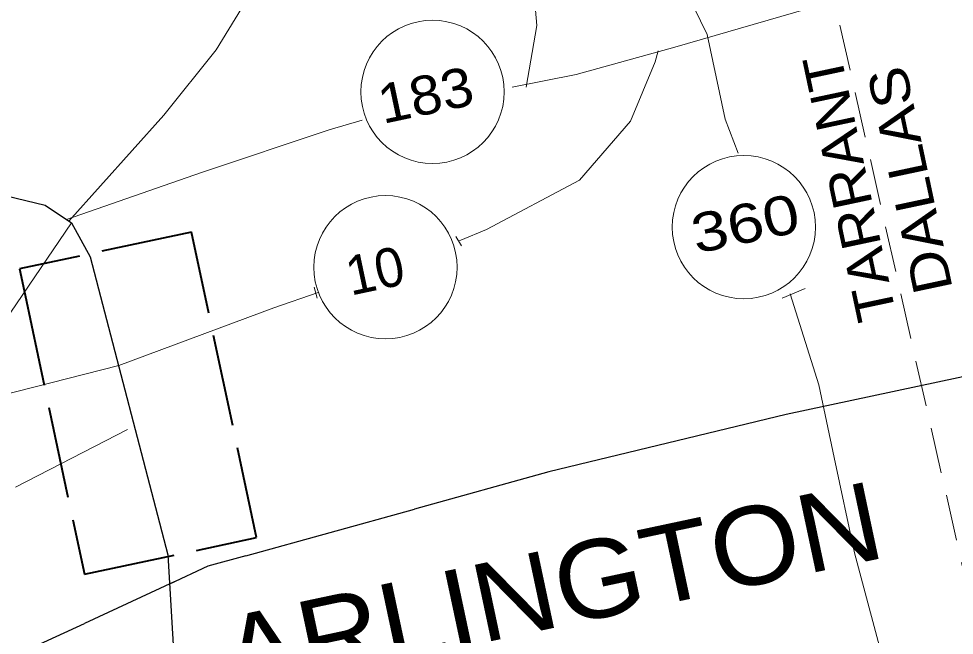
# Model space of a CAD drawing. Extents: x 2357218 to 2371708, y 6973728 to 6980157.
# Drawn here: x 2357522.9 to 2357645.2, y 6974667.5 to 6974748.1 of the extents above; entities that cross this region are included whole.
import ezdxf

# ---------------------------------------------------------------- set-up
doc = ezdxf.new("R2010")
doc.units = 0
doc.header["$LTSCALE"] = 2
doc.linetypes.add('LONG_DASHED', pattern=[7.5, 6, -1.5])
doc.linetypes.add('MEDIUM_DASHED', pattern=[4.5, 3, -1.5])
doc.layers.add('62', color=7, linetype='Continuous', lineweight=13)
doc.layers.add('63', color=7, linetype='Continuous', lineweight=13)

msp = doc.modelspace()

# ---------------------------------------------------------------- linework, layer by layer
at = {"layer": '62', "linetype": 'MEDIUM_DASHED'}
msp.add_line((2357608.391, 6974843.78), (2357670.463, 6974569.716), dxfattribs=at)
at = {"layer": '62'}
for p, q in [((2357548.716, 6974744.002), (2357555.342, 6974754.934)), ((2357612.906, 6974746.026), (2357615.266, 6974734.934)), ((2357606.095, 6974742.461), (2357606.484, 6974743.878)), ((2357595.779, 6974740.777), (2357587.405, 6974739.157)), ((2357563.473, 6974733.564), (2357567.781, 6974734.825)), ((2357615.266, 6974734.934), (2357616.963, 6974730.511)), ((2357529.782, 6974721.388), (2357494.082, 6974668.875)), ((2357584.049, 6974720.525), (2357580.707, 6974719.146)), ((2357580.057, 6974719.607), (2357580.778, 6974718.38)), ((2357580.386, 6974719.031), (2357580.707, 6974719.146)), ((2357561.523, 6974712.977), (2357561.915, 6974711.566)), ((2357622.696, 6974711.552), (2357625.691, 6974712.833)), ((2357556.226, 6974710.287), (2357562.056, 6974712.306)), ((2357627.492, 6974700.242), (2357623.746, 6974712.121)), ((2357528.402, 6974689.897), (2357537.133, 6974694.379)), ((2357522.449, 6974686.841), (2357528.402, 6974689.897))]:
    msp.add_line(p, q, dxfattribs=at)
at = {"layer": '62', "lineweight": 25}
for p, q in [((2357529.782, 6974721.388), (2357532.218, 6974716.961)), ((2357532.218, 6974716.962), (2357542.389, 6974677.99)), ((2357552.581, 6974677.856), (2357574.636, 6974683.971)), ((2357543.23, 6974674.464), (2357531.481, 6974669.021)), ((2357525.137, 6974666.085), (2357531.481, 6974669.021))]:
    msp.add_line(p, q, dxfattribs=at)
at = {"layer": '62'}
for points in [[(2357612.906, 6974746.026), (2357600.131, 6974772.25), (2357585.724, 6974789.274)], [(2357595.779, 6974740.777), (2357608.657, 6974744.365), (2357631.126, 6974750.887), (2357652.256, 6974754.413), (2357666.337, 6974756.671), (2357684.011, 6974760.219), (2357693.6, 6974764.79), (2357703.731, 6974774.259), (2357715.298, 6974783.597), (2357718.976, 6974785.553)], [(2357589.228, 6974739.131), (2357590.624, 6974747.179), (2357590.131, 6974752.736)], [(2357548.716, 6974744.002), (2357541.879, 6974735.46), (2357529.457, 6974721.619)], [(2357584.049, 6974720.525), (2357596.207, 6974726.972), (2357602.867, 6974734.714), (2357606.095, 6974742.461)], [(2357529.137, 6974721.827), (2357546.802, 6974727.997), (2357563.473, 6974733.564)], [(2357556.226, 6974710.287), (2357535.978, 6974702.736), (2357489.081, 6974690.789), (2357482.118, 6974688.043)], [(2357627.492, 6974700.242), (2357629.511, 6974690.734), (2357632.166, 6974678.254), (2357636.479, 6974662.08)]]:
    msp.add_lwpolyline(points, dxfattribs=at)
at = {"layer": '62', "lineweight": 25}
for points in [[(2357731.323, 6974727.465), (2357718.735, 6974723.478), (2357699.754, 6974716.569), (2357676.809, 6974708.817), (2357651.65, 6974702.388), (2357623.234, 6974696.348), (2357592.187, 6974688.85), (2357574.636, 6974683.971)], [(2357426.636, 6974677.632), (2357435.051, 6974686.092), (2357447.82, 6974693.662), (2357456.605, 6974700.382), (2357465.446, 6974706.953), (2357476.319, 6974714.14), (2357482.491, 6974718.329), (2357492.265, 6974720.406), (2357507.868, 6974723.722), (2357519.974, 6974725.216), (2357526.369, 6974723.698), (2357529.782, 6974721.388)], [(2357542.389, 6974677.989), (2357543.196, 6974664.013), (2357544.313, 6974651.62)], [(2357552.581, 6974677.856), (2357547.604, 6974676.5), (2357542.602, 6974674.17)]]:
    msp.add_lwpolyline(points, dxfattribs=at)
at = {"layer": '62', "linetype": 'LONG_DASHED', "lineweight": 40}
msp.add_lwpolyline([(2357523.717, 6974711.934), (2357531.47, 6974675.463), (2357553.987, 6974680.247), (2357545.5, 6974720.173), (2357522.983, 6974715.389)], close=True, dxfattribs=at)
at = {"layer": '62'}
for centre in [(2357576.995, 6974738.519), (2357617.695, 6974720.846), (2357570.841, 6974715.596)]:
    msp.add_circle(centre, 9.364, dxfattribs=at)
at = {"layer": '63', "linetype": 'MEDIUM_DASHED'}
msp.add_line((2357608.391, 6974843.78), (2357670.463, 6974569.716), dxfattribs=at)
at = {"layer": '63'}
for p, q in [((2357548.716, 6974744.002), (2357555.342, 6974754.934)), ((2357612.906, 6974746.026), (2357615.266, 6974734.934)), ((2357606.095, 6974742.461), (2357606.484, 6974743.878)), ((2357595.779, 6974740.777), (2357587.405, 6974739.157)), ((2357563.473, 6974733.564), (2357567.781, 6974734.825)), ((2357615.266, 6974734.934), (2357616.963, 6974730.511)), ((2357529.782, 6974721.388), (2357494.082, 6974668.875)), ((2357584.049, 6974720.525), (2357580.707, 6974719.146)), ((2357580.057, 6974719.607), (2357580.778, 6974718.38)), ((2357580.386, 6974719.031), (2357580.707, 6974719.146)), ((2357561.523, 6974712.977), (2357561.915, 6974711.566)), ((2357622.696, 6974711.552), (2357625.691, 6974712.833)), ((2357556.226, 6974710.287), (2357562.056, 6974712.306)), ((2357627.492, 6974700.242), (2357623.746, 6974712.121)), ((2357528.402, 6974689.897), (2357537.133, 6974694.379)), ((2357522.449, 6974686.841), (2357528.402, 6974689.897))]:
    msp.add_line(p, q, dxfattribs=at)
at = {"layer": '63', "lineweight": 25}
for p, q in [((2357529.782, 6974721.388), (2357532.218, 6974716.961)), ((2357532.218, 6974716.962), (2357542.389, 6974677.99)), ((2357552.581, 6974677.856), (2357574.636, 6974683.971)), ((2357543.23, 6974674.464), (2357531.481, 6974669.021)), ((2357525.137, 6974666.085), (2357531.481, 6974669.021))]:
    msp.add_line(p, q, dxfattribs=at)
at = {"layer": '63'}
for points in [[(2357612.906, 6974746.026), (2357600.131, 6974772.25), (2357585.724, 6974789.274)], [(2357595.779, 6974740.777), (2357608.657, 6974744.365), (2357631.126, 6974750.887), (2357652.256, 6974754.413), (2357666.337, 6974756.671), (2357684.011, 6974760.219), (2357693.6, 6974764.79), (2357703.731, 6974774.259), (2357715.298, 6974783.597), (2357718.976, 6974785.553)], [(2357589.228, 6974739.131), (2357590.624, 6974747.179), (2357590.131, 6974752.736)], [(2357548.716, 6974744.002), (2357541.879, 6974735.46), (2357529.457, 6974721.619)], [(2357584.049, 6974720.525), (2357596.207, 6974726.972), (2357602.867, 6974734.714), (2357606.095, 6974742.461)], [(2357529.137, 6974721.827), (2357546.802, 6974727.997), (2357563.473, 6974733.564)], [(2357556.226, 6974710.287), (2357535.978, 6974702.736), (2357489.081, 6974690.789), (2357482.118, 6974688.043)], [(2357627.492, 6974700.242), (2357629.511, 6974690.734), (2357632.166, 6974678.254), (2357636.479, 6974662.08)]]:
    msp.add_lwpolyline(points, dxfattribs=at)
at = {"layer": '63', "lineweight": 25}
for points in [[(2357731.323, 6974727.465), (2357718.735, 6974723.478), (2357699.754, 6974716.569), (2357676.809, 6974708.817), (2357651.65, 6974702.388), (2357623.234, 6974696.348), (2357592.187, 6974688.85), (2357574.636, 6974683.971)], [(2357426.636, 6974677.632), (2357435.051, 6974686.092), (2357447.82, 6974693.662), (2357456.605, 6974700.382), (2357465.446, 6974706.953), (2357476.319, 6974714.14), (2357482.491, 6974718.329), (2357492.265, 6974720.406), (2357507.868, 6974723.722), (2357519.974, 6974725.216), (2357526.369, 6974723.698), (2357529.782, 6974721.388)], [(2357542.389, 6974677.989), (2357543.196, 6974664.013), (2357544.313, 6974651.62)], [(2357552.581, 6974677.856), (2357547.604, 6974676.5), (2357542.602, 6974674.17)]]:
    msp.add_lwpolyline(points, dxfattribs=at)
at = {"layer": '63', "linetype": 'LONG_DASHED', "lineweight": 40}
msp.add_lwpolyline([(2357523.717, 6974711.934), (2357531.47, 6974675.463), (2357553.987, 6974680.247), (2357545.5, 6974720.173), (2357522.983, 6974715.389)], close=True, dxfattribs=at)
at = {"layer": '63'}
for centre in [(2357576.995, 6974738.519), (2357617.695, 6974720.846), (2357570.841, 6974715.596)]:
    msp.add_circle(centre, 9.364, dxfattribs=at)

# ---------------------------------------------------------------- texts
at = {"layer": '62'}
for s, height, rotation, width, p in [('TARRANT', 5.099, 102, 1.1, (2357637.672, 6974709.171)), ('183', 5.099, 12, 1.1, (2357570.489, 6974734.321)), ('DALLAS', 5.099, 102, 1.15, (2357645.026, 6974712.781)), ('360', 5.099, 12, 1.25, (2357611.456, 6974717.353)), ('ARLINGTON', 10.21, 12, 1.1, (2357550.803, 6974659.511))]:
    msp.add_text(s, height=height, rotation=rotation, dxfattribs=dict(at, width=width)).set_placement(p)
msp.add_text('10', height=5.099, rotation=12, dxfattribs=at).set_placement((2357566.289, 6974711.873))
at = {"layer": '63'}
for s, height, rotation, width, p in [('TARRANT', 5.099, 102, 1.1, (2357637.672, 6974709.171)), ('183', 5.099, 12, 1.1, (2357570.489, 6974734.321)), ('DALLAS', 5.099, 102, 1.15, (2357645.026, 6974712.781)), ('360', 5.099, 12, 1.25, (2357611.456, 6974717.353)), ('ARLINGTON', 10.21, 12, 1.1, (2357550.803, 6974659.511))]:
    msp.add_text(s, height=height, rotation=rotation, dxfattribs=dict(at, width=width)).set_placement(p)
msp.add_text('10', height=5.099, rotation=12, dxfattribs=at).set_placement((2357566.289, 6974711.873))

doc.saveas('drawing.dxf')
